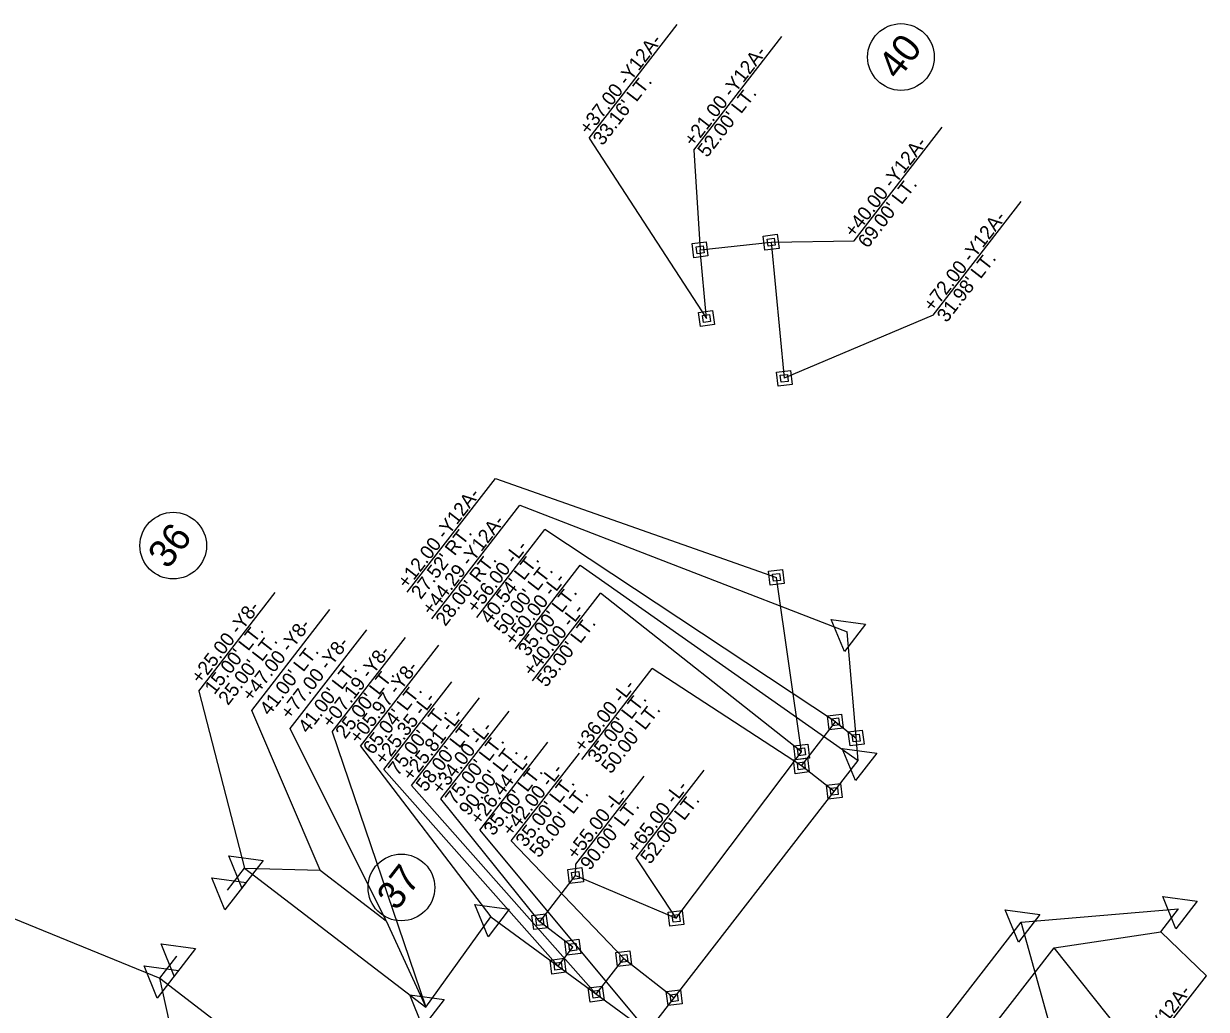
# Model space of a CAD drawing. Extents: x 2010883 to 2014849, y 442000 to 447413.
# Drawn here: x 2014399.8 to 2014825.4, y 445967.7 to 446322.4 of the extents above; entities that cross this region are included whole.
import ezdxf

# ---------------------------------------------------------------- set-up
doc = ezdxf.new("R2010")
doc.units = 0
for name, color, linetype in [('Prop Easement Construction', 7, 'Continuous'), ('Prop Easement Construction Station Offsets', 7, 'Continuous'), ('Prop Easement Permanent Drainage Station Offsets', 7, 'Continuous'), ('Prop Easement Permanent Drainage Utility', 7, 'Continuous'), ('Prop Easement Permanent Drainage Utility Station Offsets', 7, 'Continuous'), ('Prop Easement Permanent Utility', 7, 'Continuous'), ('Prop Easement Permanent Utility Station Offsets', 7, 'Continuous'), ('Prop Parcel Number CELL', 7, 'Continuous'), ('Prop Parcel Number Text', 7, 'Continuous'), ('Prop ROW Marker CELL', 7, 'Continuous'), ('Prop ROW Permanent Easement CELL', 7, 'Continuous'), ('Prop ROW RW Lines', 7, 'Continuous'), ('Prop ROW Station Offsets', 7, 'Continuous')]:
    doc.layers.add(name, color=color, linetype=linetype)

msp = doc.modelspace()

# ---------------------------------------------------------------- linework, layer by layer
at = {"layer": 'Prop Easement Construction'}
for p, q in [((2014479.28, 446018.52), (2014506.48, 446017.81)), ((2014506.48, 446017.81), (2014530.26, 445999.53)), ((2014809.03, 445995.54), (2014815.4, 446003.81)), ((2014530.26, 445999.53), (2014544.46, 445968.44)), ((2014770.62, 445989.83), (2014809.03, 445995.54)), ((2014733.85, 445942.42), (2014770.62, 445989.83)), ((2014455.84, 445946.99), (2014448.82, 445978.88))]:
    msp.add_line(p, q, dxfattribs=at)
at = {"layer": 'Prop Easement Construction Station Offsets'}
for p, q in [((2014481.83, 446075.17), (2014510.02, 446111.52)), ((2014495.67, 446068.72), (2014523.25, 446104.28)), ((2014506.48, 446017.81), (2014481.83, 446075.17)), ((2014530.26, 445999.53), (2014495.67, 446068.72)), ((2014794.51, 445959.85), (2014770.62, 445989.83))]:
    msp.add_line(p, q, dxfattribs=at)
at = {"layer": 'Prop Easement Permanent Drainage Station Offsets'}
for p, q in [((2014562.85, 446108.74), (2014587.37, 446140.34)), ((2014691.92, 446071.11), (2014587.37, 446140.34)), ((2014539.37, 446048.19), (2014563.88, 446079.8)), ((2014605.81, 445973.14), (2014539.37, 446048.19))]:
    msp.add_line(p, q, dxfattribs=at)
at = {"layer": 'Prop Easement Permanent Drainage Utility'}
for p, q in [((2014679.66, 446055.31), (2014691.92, 446071.11)), ((2014691.92, 446071.11), (2014699.4, 446065.31)), ((2014691.51, 446046.12), (2014679.66, 446055.31)), ((2014605.81, 445973.14), (2014615.73, 445985.93)), ((2014615.73, 445985.93), (2014633.91, 445971.84))]:
    msp.add_line(p, q, dxfattribs=at)
at = {"layer": 'Prop Easement Permanent Drainage Utility Station Offsets'}
for p, q in [((2014600.62, 446057.54), (2014626.01, 446090.28)), ((2014679.66, 446055.31), (2014626.01, 446090.28)), ((2014575.28, 446028.3), (2014599.79, 446059.91)), ((2014615.73, 445985.93), (2014575.28, 446028.3))]:
    msp.add_line(p, q, dxfattribs=at)
at = {"layer": 'Prop Easement Permanent Utility'}
for p, q in [((2014643.21, 446241.03), (2014668.78, 446243.76)), ((2014645.53, 446216.31), (2014643.21, 446241.03)), ((2014668.78, 446243.76), (2014673.52, 446194.79)), ((2014679.74, 446060.31), (2014670.69, 446123.14)), ((2014634.57, 446000.43), (2014679.74, 446060.31)), ((2014585.54, 445999.22), (2014598.41, 446015.82)), ((2014598.41, 446015.82), (2014634.57, 446000.43)), ((2014597.4, 445990.03), (2014585.54, 445999.22)), ((2014592.1, 445983.19), (2014597.4, 445990.03))]:
    msp.add_line(p, q, dxfattribs=at)
at = {"layer": 'Prop Easement Permanent Utility Station Offsets'}
for p, q in [((2014603.25, 446281.17), (2014634.98, 446322.08)), ((2014640.92, 446276.92), (2014672.64, 446317.82)), ((2014698.67, 446244.22), (2014730.39, 446285.13)), ((2014603.25, 446281.17), (2014645.53, 446216.31)), ((2014640.92, 446276.92), (2014643.21, 446241.03)), ((2014727.1, 446217.49), (2014758.82, 446258.4)), ((2014668.78, 446243.76), (2014698.67, 446244.22)), ((2014727.1, 446217.49), (2014673.52, 446194.79)), ((2014537.83, 446117.84), (2014569.55, 446158.75)), ((2014569.55, 446158.75), (2014670.69, 446123.14)), ((2014582.85, 446085.84), (2014607.36, 446117.45)), ((2014679.74, 446060.31), (2014607.36, 446117.45)), ((2014529.41, 446053.95), (2014553.92, 446085.56)), ((2014549.94, 446043.4), (2014574.45, 446075.01)), ((2014592.1, 445983.19), (2014529.41, 446053.95)), ((2014620.2, 446022.18), (2014644.72, 446053.78)), ((2014598.53, 446019.95), (2014623.04, 446051.55)), ((2014585.54, 445999.22), (2014549.94, 446043.4)), ((2014598.41, 446015.82), (2014598.53, 446019.95)), ((2014634.57, 446000.43), (2014620.2, 446022.18))]:
    msp.add_line(p, q, dxfattribs=at)
at = {"layer": 'Prop Parcel Number CELL'}
for p, q in [((2014715.52, 446310.42), (2014715.52, 446310.42)), ((2014453.6, 446134.55), (2014453.6, 446134.55)), ((2014535.7, 446011.52), (2014535.7, 446011.52))]:
    msp.add_line(p, q, dxfattribs=at)
for centre in [(2014715.52, 446310.42), (2014453.6, 446134.55), (2014535.7, 446011.52)]:
    msp.add_circle(centre, 12, dxfattribs=at)
at = {"layer": 'Prop ROW Marker CELL'}
for p, q in [((2014643.21, 446241.03), (2014643.21, 446241.03)), ((2014668.78, 446243.76), (2014668.78, 446243.76)), ((2014645.53, 446216.31), (2014645.53, 446216.31)), ((2014673.52, 446194.79), (2014673.52, 446194.79)), ((2014670.69, 446123.14), (2014670.69, 446123.14)), ((2014696.11, 446103.59), (2014696.11, 446103.59)), ((2014691.92, 446071.11), (2014691.92, 446071.11)), ((2014699.4, 446065.31), (2014699.4, 446065.31)), ((2014679.74, 446060.31), (2014679.74, 446060.31)), ((2014700.09, 446057.18), (2014700.09, 446057.18)), ((2014679.66, 446055.31), (2014679.66, 446055.31)), ((2014691.51, 446046.12), (2014691.51, 446046.12)), ((2014479.28, 446018.52), (2014479.28, 446018.52)), ((2014598.41, 446015.82), (2014598.41, 446015.82)), ((2014473.19, 446010.59), (2014473.19, 446010.59)), ((2014815.4, 446003.81), (2014815.4, 446003.81)), ((2014567.88, 446000.94), (2014567.88, 446000.94)), ((2014585.54, 445999.22), (2014585.54, 445999.22)), ((2014634.57, 446000.43), (2014634.57, 446000.43)), ((2014758.76, 445999.02), (2014758.76, 445999.02)), ((2014597.4, 445990.03), (2014597.4, 445990.03)), ((2014454.91, 445986.81), (2014454.91, 445986.81)), ((2014615.73, 445985.93), (2014615.73, 445985.93)), ((2014592.1, 445983.19), (2014592.1, 445983.19)), ((2014448.82, 445978.88), (2014448.82, 445978.88)), ((2014605.81, 445973.14), (2014605.81, 445973.14)), ((2014544.46, 445968.44), (2014544.46, 445968.44)), ((2014633.91, 445971.84), (2014633.91, 445971.84))]:
    msp.add_line(p, q, dxfattribs=at)
for points in [[(2014695.13, 446096.44), (2014690.42, 446108), (2014702.79, 446106.32)], [(2014699.11, 446050.03), (2014694.41, 446061.59), (2014706.77, 446059.91)], [(2014478.3, 446011.38), (2014473.59, 446022.94), (2014485.96, 446021.26)], [(2014472.2, 446003.45), (2014467.5, 446015.01), (2014479.87, 446013.33)], [(2014814.42, 445996.67), (2014809.71, 446008.22), (2014822.08, 446006.54)], [(2014566.89, 445993.79), (2014562.19, 446005.35), (2014574.56, 446003.67)], [(2014757.78, 445991.88), (2014753.07, 446003.44), (2014765.44, 446001.76)], [(2014453.93, 445979.66), (2014449.22, 445991.22), (2014461.59, 445989.54)], [(2014447.83, 445971.73), (2014443.13, 445983.29), (2014455.49, 445981.61)], [(2014543.47, 445961.3), (2014538.77, 445972.85), (2014551.13, 445971.17)]]:
    msp.add_lwpolyline(points, close=True, dxfattribs=at)
at = {"layer": 'Prop ROW Permanent Easement CELL'}
for points in [[(2014665.93, 446245.96), (2014670.98, 446246.6), (2014671.62, 446241.55), (2014666.57, 446240.91)], [(2014667.36, 446244.86), (2014669.88, 446245.18), (2014670.2, 446242.66), (2014667.67, 446242.34)], [(2014640.37, 446243.24), (2014645.42, 446243.88), (2014646.06, 446238.83), (2014641.01, 446238.19)], [(2014641.79, 446242.13), (2014644.32, 446242.45), (2014644.63, 446239.93), (2014642.11, 446239.61)], [(2014642.68, 446218.51), (2014647.73, 446219.15), (2014648.37, 446214.1), (2014643.32, 446213.46)], [(2014644.11, 446217.41), (2014646.63, 446217.73), (2014646.95, 446215.2), (2014644.42, 446214.88)], [(2014670.67, 446197), (2014675.72, 446197.63), (2014676.36, 446192.58), (2014671.31, 446191.94)], [(2014672.09, 446195.89), (2014674.62, 446196.21), (2014674.94, 446193.69), (2014672.41, 446193.37)], [(2014667.84, 446125.34), (2014672.9, 446125.98), (2014673.53, 446120.93), (2014668.48, 446120.29)], [(2014669.27, 446124.24), (2014671.79, 446124.56), (2014672.11, 446122.03), (2014669.59, 446121.71)], [(2014689.07, 446073.32), (2014694.12, 446073.96), (2014694.76, 446068.91), (2014689.71, 446068.27)], [(2014690.5, 446072.22), (2014693.02, 446072.54), (2014693.34, 446070.01), (2014690.82, 446069.69)], [(2014696.55, 446067.52), (2014701.6, 446068.16), (2014702.24, 446063.11), (2014697.19, 446062.47)], [(2014697.97, 446066.42), (2014700.5, 446066.74), (2014700.82, 446064.21), (2014698.29, 446063.89)], [(2014676.9, 446062.51), (2014681.95, 446063.15), (2014682.59, 446058.1), (2014677.54, 446057.46)], [(2014678.32, 446061.41), (2014680.85, 446061.73), (2014681.16, 446059.21), (2014678.64, 446058.89)], [(2014676.82, 446057.52), (2014681.87, 446058.15), (2014682.51, 446053.1), (2014677.46, 446052.46)], [(2014678.24, 446056.41), (2014680.76, 446056.73), (2014681.08, 446054.21), (2014678.56, 446053.89)], [(2014688.67, 446048.32), (2014693.72, 446048.96), (2014694.36, 446043.91), (2014689.31, 446043.27)], [(2014690.09, 446047.22), (2014692.62, 446047.54), (2014692.94, 446045.01), (2014690.41, 446044.69)], [(2014595.57, 446018.02), (2014600.62, 446018.66), (2014601.26, 446013.61), (2014596.21, 446012.97)], [(2014596.99, 446016.92), (2014599.52, 446017.24), (2014599.84, 446014.71), (2014597.31, 446014.39)], [(2014582.7, 446001.43), (2014587.75, 446002.07), (2014588.39, 445997.02), (2014583.34, 445996.38)], [(2014631.73, 446002.64), (2014636.78, 446003.27), (2014637.41, 445998.22), (2014632.36, 445997.59)], [(2014633.15, 446001.53), (2014635.67, 446001.85), (2014635.99, 445999.33), (2014633.47, 445999.01)], [(2014584.12, 446000.32), (2014586.65, 446000.64), (2014586.97, 445998.12), (2014584.44, 445997.8)], [(2014594.55, 445992.23), (2014599.6, 445992.87), (2014600.24, 445987.82), (2014595.19, 445987.18)], [(2014595.97, 445991.13), (2014598.5, 445991.45), (2014598.82, 445988.93), (2014596.29, 445988.61)], [(2014589.25, 445985.4), (2014594.3, 445986.04), (2014594.94, 445980.99), (2014589.89, 445980.35)], [(2014612.89, 445988.14), (2014617.94, 445988.78), (2014618.58, 445983.73), (2014613.53, 445983.09)], [(2014614.31, 445987.04), (2014616.84, 445987.35), (2014617.16, 445984.83), (2014614.63, 445984.51)], [(2014590.67, 445984.3), (2014593.2, 445984.61), (2014593.52, 445982.09), (2014590.99, 445981.77)], [(2014602.97, 445975.35), (2014608.02, 445975.98), (2014608.66, 445970.93), (2014603.61, 445970.3)], [(2014604.39, 445974.24), (2014606.92, 445974.56), (2014607.23, 445972.04), (2014604.71, 445971.72)], [(2014631.06, 445974.04), (2014636.11, 445974.68), (2014636.75, 445969.63), (2014631.7, 445968.99)], [(2014632.49, 445972.94), (2014635.01, 445973.26), (2014635.33, 445970.73), (2014632.81, 445970.41)]]:
    msp.add_lwpolyline(points, close=True, dxfattribs=at)
at = {"layer": 'Prop ROW RW Lines'}
for p, q in [((2014700.09, 446057.18), (2014696.11, 446103.59)), ((2014624.37, 445959.54), (2014700.09, 446057.18)), ((2014473.19, 446010.59), (2014479.28, 446018.52)), ((2014479.28, 446018.52), (2014544.46, 445968.44)), ((2014758.76, 445999.02), (2014815.4, 446003.81)), ((2014544.46, 445968.44), (2014567.88, 446000.94)), ((2014567.88, 446000.94), (2014624.37, 445959.54)), ((2014674.8, 445890.77), (2014758.76, 445999.02)), ((2014448.82, 445978.88), (2014454.91, 445986.81)), ((2014448.82, 445978.88), (2014488.28, 445948.55))]:
    msp.add_line(p, q, dxfattribs=at)
at = {"layer": 'Prop ROW Station Offsets'}
for p, q in [((2014546.66, 446108.17), (2014578.39, 446149.07)), ((2014578.39, 446149.07), (2014696.11, 446103.59)), ((2014576.78, 446097.46), (2014600.06, 446127.49)), ((2014600.06, 446127.49), (2014700.09, 446057.18)), ((2014462.76, 446082.19), (2014490.34, 446117.74)), ((2014510.82, 446067.54), (2014537.17, 446101.52)), ((2014521.01, 446062.44), (2014549.2, 446098.79)), ((2014462.76, 446082.19), (2014479.28, 446018.52)), ((2014510.82, 446067.54), (2014544.46, 445968.44)), ((2014521.01, 446062.44), (2014567.88, 446000.94)), ((2014563.93, 446032.16), (2014588.44, 446063.77)), ((2014563.93, 446032.16), (2014624.37, 445959.54)), ((2014377.15, 446008.13), (2014448.82, 445978.88)), ((2014773.39, 445946.91), (2014758.76, 445999.02)), ((2014825.42, 445979.76), (2014809.03, 445995.54)), ((2014794.16, 445939.46), (2014825.42, 445979.76))]:
    msp.add_line(p, q, dxfattribs=at)

# ---------------------------------------------------------------- texts
at = {"layer": 'Prop Easement Construction Station Offsets'}
for s, p in [('+47.00 -Y8-', (2014481.78, 446078.09)), ('+77.00 -Y8-', (2014495.62, 446071.64)), ("41.00' LT.", (2014488.2, 446073.11)), ("41.00' LT.", (2014502.04, 446066.67))]:
    msp.add_text(s, height=5, rotation=52.2051, dxfattribs=at).set_placement(p)
at = {"layer": 'Prop Easement Permanent Drainage Station Offsets'}
for s, p in [('+56.00 -L-', (2014562.63, 446109.88)), ("40.54' LT.", (2014567.57, 446106.05)), ("50.00' LT.", (2014572.5, 446102.22)), ('+25.81 -L-', (2014539.47, 446049.46)), ("58.00' LT.", (2014544.41, 446045.63))]:
    msp.add_text(s, height=5, rotation=52.2051, dxfattribs=at).set_placement(p)
at = {"layer": 'Prop Easement Permanent Drainage Utility Station Offsets'}
for s, p in [('+36.00 -L-', (2014601.27, 446059.82)), ("35.00' LT.", (2014606.21, 446055.99)), ("50.00' LT.", (2014611.15, 446052.16)), ('+42.00 -L-', (2014575.38, 446029.57)), ("35.00' LT.", (2014580.32, 446025.74)), ("58.00' LT.", (2014585.26, 446021.9))]:
    msp.add_text(s, height=5, rotation=52.2051, dxfattribs=at).set_placement(p)
at = {"layer": 'Prop Easement Permanent Utility Station Offsets'}
for s, p in [('+37.00 -Y12A-', (2014603.17, 446282.08)), ('+21.00 -Y12A-', (2014640.84, 446277.82)), ("33.16' LT.", (2014608.11, 446278.25)), ("52.00' LT.", (2014645.77, 446273.99)), ('+40.00 -Y12A-', (2014698.58, 446245.12)), ("69.00' LT.", (2014703.52, 446241.29)), ('+72.00 -Y12A-', (2014727.02, 446218.4)), ("31.98' LT.", (2014731.95, 446214.57)), ('+12.00 -Y12A-', (2014537.75, 446118.75)), ("27.52' RT.", (2014542.69, 446114.92)), ('+40.00 -L-', (2014582.94, 446087.11)), ("53.00' LT.", (2014587.88, 446083.28)), ('+25.35 -L-', (2014529.51, 446055.22)), ("75.00' LT.", (2014534.44, 446051.39)), ('+34.00 -L-', (2014550.03, 446044.67)), ("75.00' LT.", (2014554.97, 446040.84)), ("90.00' LT.", (2014559.91, 446037.01)), ('+65.00 -L-', (2014620.3, 446023.44)), ('+55.00 -L-', (2014598.62, 446021.21)), ("52.00' LT.", (2014625.24, 446019.61)), ("90.00' LT.", (2014603.56, 446017.38))]:
    msp.add_text(s, height=5, rotation=52.2051, dxfattribs=at).set_placement(p)
at = {"layer": 'Prop Parcel Number Text'}
for s, p in [('40', (2014714.42, 446301.82)), ('36', (2014451.63, 446125.76)), ('37', (2014533.99, 446002.82))]:
    msp.add_text(s, height=10, rotation=52.2051, dxfattribs=at).set_placement(p)
at = {"layer": 'Prop ROW Station Offsets'}
for s, p in [('+44.29 -Y12A-', (2014546.58, 446109.07)), ("28.00' RT.", (2014551.52, 446105.24)), ('+50.00 -L-', (2014576.24, 446098.19)), ("35.00' LT.", (2014581.18, 446094.36)), ('+25.00 -Y8-', (2014463.46, 446084.48)), ("15.00' LT.", (2014468.4, 446080.65)), ("25.00' LT.", (2014473.34, 446076.82)), ('+07.19 -Y8-', (2014510.51, 446068.56)), ('+05.97 -Y8-', (2014520.47, 446062.86)), ("25.00' LT.", (2014515.45, 446064.73)), ("65.04' LT.", (2014525.4, 446059.03)), ('+26.44 -L-', (2014563.88, 446033.67)), ("35.00' LT.", (2014568.82, 446029.84)), ('+00.00 -Y12A-', (2014793.54, 445939.86))]:
    msp.add_text(s, height=5, rotation=52.2051, dxfattribs=at).set_placement(p)

doc.saveas('drawing.dxf')
